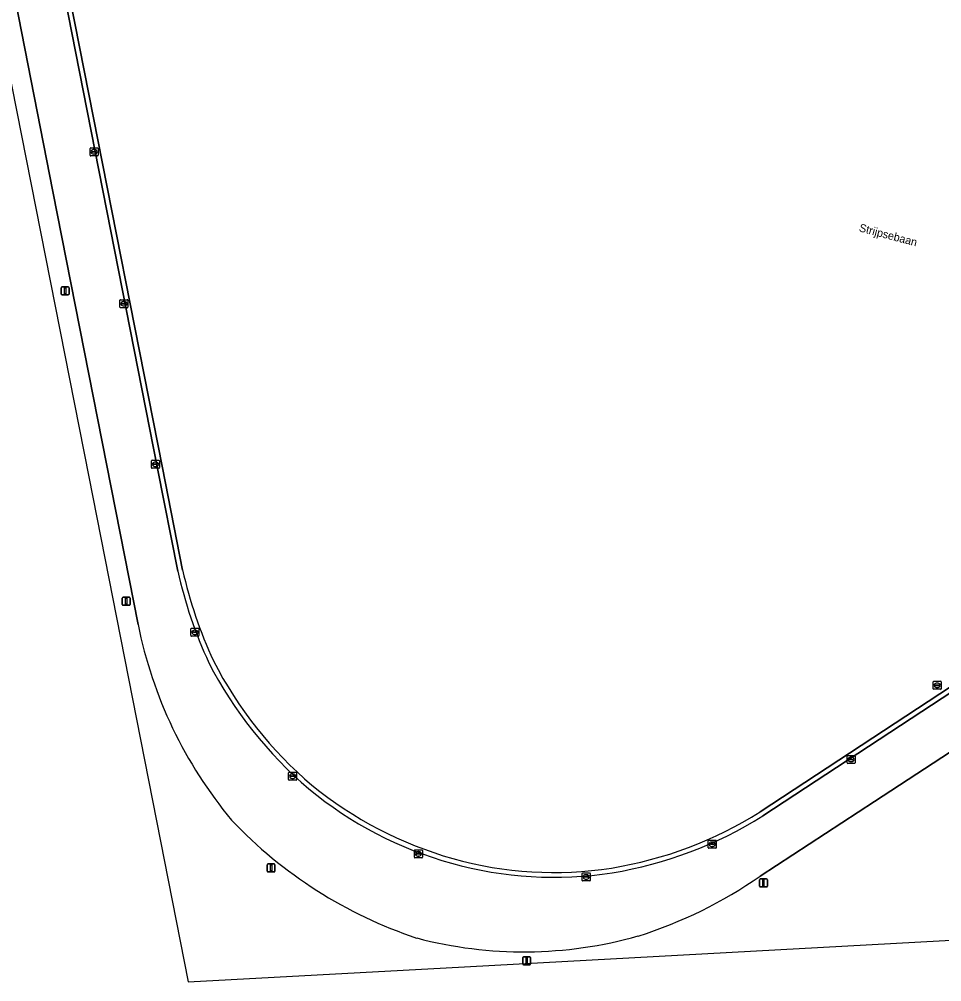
# Model space of a CAD drawing. Extents: x 154324 to 155744, y 382937 to 384188.
# Drawn here: x 154446.7 to 154562, y 382936.9 to 383057.2 of the extents above; entities that cross this region are included whole.
import ezdxf

# ---------------------------------------------------------------- set-up
doc = ezdxf.new("R2010")
doc.units = 0
for name, color, linetype in [('IMGEO_Bouwland', 7, 'Continuous'), ('IMGEO_Brandkraan', 7, 'Continuous'), ('IMGEO_Kolk', 7, 'Continuous'), ('IMGEO_Lichtmast', 7, 'Continuous'), ('IMGEO_Openbare_ruimte_label', 7, 'Continuous'), ('IMGEO_Rijbaan_lokaal_gesloten', 7, 'Continuous')]:
    doc.layers.add(name, color=color, linetype=linetype)

msp = doc.modelspace()

# ---------------------------------------------------------------- linework, layer by layer
at = {"layer": 'IMGEO_Bouwland'}
for points in [[(154461.51, 382981.55), (154450.87, 383035.65), (154439.15, 383095.25), (154422.31, 383181.22), (154406.72, 383260.28), (154396.48, 383312.17), (154394.42, 383322.32), (154392.95, 383329.96)], [(154562.03, 383175.54), (154561.39, 383175.43), (154560.93, 383178.26), (154468.8, 383162.6), (154469.46, 383158.8), (154442.14, 383154.08), (154422.8, 383252.54), (154415.36, 383251.02), (154421.39, 383220.37), (154444.99, 383100.45), (154464.56, 383001.13), (154467.07, 382988.35)], [(154438.84, 383056.38), (154444.54, 383054.87), (154455.34, 383000), (154467.76, 382936.91), (154500, 382938.67), (154564.68, 382942.19), (154564.68, 382942.19), (154613.01, 382968.97), (154623.86, 382975.26)], [(154539.26, 382958.13), (154607.95, 383003.23)], [(154607.05, 382994.38), (154553.54, 382959.42), (154539.25, 382950.1)]]:
    msp.add_lwpolyline(points, dxfattribs=at)
for centre, radius, start, end in [((154523.54, 383001.26), 57.93, 192.8711, 204.7457), ((154515.59, 382992.4), 55.16, 191.3377, 219.7864), ((154515.81, 382999.9), 50.38, 207.0226, 229.7267), ((154514.19, 382999.44), 48.99, 230.8269, 254.2103), ((154512.69, 383000.44), 49.96, 279.1993, 302.1275), ((154514.24, 382996.02), 56.56, 223.4828, 251.5325), ((154513.49, 382997.32), 46.76, 254.3311, 278.8421), ((154506.9, 382996.74), 56.76, 287.5622, 304.7459), ((154509.71, 382993.24), 52.59, 255.2615, 285.7936)]:
    msp.add_arc(centre, radius, start, end, dxfattribs=at)
at = {"layer": 'IMGEO_Brandkraan'}
for p, q in [((154560.89, 382973.52), (154560.89, 382974.37)), ((154560.96, 382974.45), (154561.81, 382974.45)), ((154561.89, 382974.37), (154561.89, 382973.52)), ((154561.81, 382973.45), (154560.96, 382973.45)), ((154561.14, 382973.94), (154561.14, 382973.95)), ((154561.58, 382973.9), (154561.18, 382973.9)), ((154561.19, 382973.99), (154561.59, 382973.99)), ((154561.37, 382974.23), (154561.4, 382974.23)), ((154561.4, 382973.67), (154561.37, 382973.67)), ((154561.63, 382973.95), (154561.63, 382973.94))]:
    msp.add_line(p, q, dxfattribs=at)
for points in [[(154560.89, 382973.52), (154560.89, 382974.37)], [(154560.96, 382974.45), (154561.81, 382974.45)], [(154561.89, 382974.37), (154561.89, 382973.52)], [(154561.81, 382973.45), (154560.96, 382973.45)]]:
    msp.add_lwpolyline(points, dxfattribs=at)
for centre, radius, start, end in [((154560.96, 382974.37), 0.0765, 91.552, 178.448), ((154560.96, 382974.37), 0.0765, 91.552, 178.448), ((154561.81, 382974.37), 0.0765, 1.552, 88.448), ((154561.81, 382974.37), 0.0765, 1.552, 88.448), ((154560.96, 382973.52), 0.0765, 181.552, 268.448), ((154560.96, 382973.52), 0.0765, 181.552, 268.448), ((154561.19, 382973.95), 0.0403, 85.8775, 175.7526), ((154561.18, 382973.94), 0.0366, 178.938, 274.7102), ((154561.59, 382973.95), 0.043, 264.8664, 352.4533), ((154561.59, 382973.95), 0.0386, 1.7309, 96.639), ((154561.81, 382973.52), 0.0765, 271.552, 358.448), ((154561.81, 382973.52), 0.0765, 271.552, 358.448)]:
    msp.add_arc(centre, radius, start, end, dxfattribs=at)
for centre, major_axis, ratio, start_param, end_param in [((154561.37, 382973.95), (-0.387, 0.002), 0.722429, 4.712389, 7.853982), ((154561.4, 382973.95), (-0.39, 0.002), 0.717154, 1.570796, 4.712389)]:
    msp.add_ellipse(centre, major_axis=major_axis, ratio=ratio, start_param=start_param, end_param=end_param, dxfattribs=at)
at = {"layer": 'IMGEO_Kolk'}
for p, q in [((154455.51, 383040.17), (154455.51, 383041.02)), ((154455.58, 383041.1), (154456.44, 383041.1)), ((154455.77, 383040.59), (154455.77, 383040.6)), ((154455.81, 383040.64), (154456.21, 383040.64)), ((154456.21, 383040.55), (154455.81, 383040.55)), ((154456, 383040.88), (154456.02, 383040.88)), ((154456.25, 383040.6), (154456.25, 383040.59)), ((154456.51, 383041.02), (154456.51, 383040.17)), ((154456.44, 383040.1), (154455.58, 383040.1)), ((154456.02, 383040.32), (154456, 383040.32)), ((154459.24, 383021.2), (154459.24, 383022.05)), ((154459.31, 383022.12), (154460.17, 383022.12)), ((154459.5, 383021.62), (154459.5, 383021.63)), ((154459.54, 383021.67), (154459.94, 383021.67)), ((154459.93, 383021.58), (154459.54, 383021.58)), ((154459.75, 383021.34), (154459.72, 383021.34)), ((154459.73, 383021.9), (154459.75, 383021.9)), ((154459.98, 383021.63), (154459.98, 383021.62)), ((154460.24, 383022.05), (154460.24, 383021.2)), ((154460.17, 383021.12), (154459.31, 383021.12)), ((154463.18, 383001.14), (154463.18, 383001.99)), ((154463.26, 383002.06), (154464.11, 383002.06)), ((154464.19, 383001.99), (154464.19, 383001.14)), ((154464.11, 383001.06), (154463.26, 383001.06)), ((154463.44, 383001.56), (154463.44, 383001.57)), ((154463.88, 383001.52), (154463.48, 383001.52)), ((154463.49, 383001.61), (154463.88, 383001.61)), ((154463.67, 383001.84), (154463.7, 383001.84)), ((154463.69, 383001.28), (154463.67, 383001.28)), ((154463.93, 383001.57), (154463.93, 383001.56)), ((154468.12, 382980.15), (154468.12, 382981)), ((154468.19, 382981.08), (154469.05, 382981.08)), ((154468.38, 382980.57), (154468.38, 382980.58)), ((154468.42, 382980.62), (154468.82, 382980.62)), ((154468.81, 382980.53), (154468.42, 382980.53)), ((154468.63, 382980.3), (154468.6, 382980.3)), ((154468.61, 382980.85), (154468.63, 382980.85)), ((154468.86, 382980.58), (154468.86, 382980.57)), ((154469.12, 382981), (154469.12, 382980.15)), ((154469.05, 382980.07), (154468.19, 382980.07)), ((154550.12, 382964.25), (154550.12, 382965.11)), ((154550.2, 382965.18), (154551.05, 382965.18)), ((154550.38, 382964.67), (154550.38, 382964.69)), ((154550.42, 382964.72), (154550.82, 382964.72)), ((154550.82, 382964.64), (154550.42, 382964.64)), ((154550.61, 382964.96), (154550.63, 382964.96)), ((154550.86, 382964.69), (154550.86, 382964.67)), ((154551.12, 382965.11), (154551.12, 382964.25)), ((154551.05, 382964.18), (154550.2, 382964.18)), ((154550.63, 382964.4), (154550.61, 382964.4)), ((154480.32, 382962.17), (154480.32, 382963.02)), ((154480.4, 382963.09), (154481.25, 382963.09)), ((154480.58, 382962.59), (154480.58, 382962.6)), ((154480.62, 382962.64), (154481.02, 382962.64)), ((154481.02, 382962.55), (154480.62, 382962.55)), ((154480.81, 382962.87), (154480.84, 382962.87)), ((154480.83, 382962.31), (154480.81, 382962.31)), ((154481.07, 382962.6), (154481.07, 382962.59)), ((154481.32, 382963.02), (154481.32, 382962.17)), ((154481.25, 382962.09), (154480.4, 382962.09)), ((154532.78, 382953.66), (154532.78, 382954.52)), ((154532.85, 382954.59), (154533.7, 382954.59)), ((154533.03, 382954.08), (154533.03, 382954.1)), ((154533.47, 382954.05), (154533.07, 382954.05)), ((154533.08, 382954.13), (154533.47, 382954.13)), ((154533.26, 382954.37), (154533.29, 382954.37)), ((154533.29, 382953.81), (154533.26, 382953.81)), ((154533.52, 382954.1), (154533.52, 382954.08)), ((154533.78, 382954.52), (154533.78, 382953.66)), ((154496.04, 382952.46), (154496.04, 382953.31)), ((154496.12, 382953.39), (154496.97, 382953.39)), ((154496.3, 382952.88), (154496.3, 382952.89)), ((154496.34, 382952.93), (154496.74, 382952.93)), ((154496.74, 382952.84), (154496.34, 382952.84)), ((154496.53, 382953.17), (154496.56, 382953.17)), ((154496.55, 382952.61), (154496.53, 382952.61)), ((154496.79, 382952.89), (154496.79, 382952.88)), ((154497.04, 382953.31), (154497.04, 382952.46)), ((154533.7, 382953.59), (154532.85, 382953.59)), ((154496.97, 382952.39), (154496.12, 382952.39)), ((154517.02, 382949.58), (154517.02, 382950.43)), ((154517.1, 382950.51), (154517.95, 382950.51)), ((154517.51, 382950.29), (154517.53, 382950.29)), ((154518.02, 382950.43), (154518.02, 382949.58)), ((154517.95, 382949.51), (154517.1, 382949.51)), ((154517.28, 382950), (154517.28, 382950.01)), ((154517.32, 382950.05), (154517.72, 382950.05)), ((154517.72, 382949.96), (154517.32, 382949.96)), ((154517.53, 382949.73), (154517.51, 382949.73)), ((154517.76, 382950.01), (154517.76, 382950))]:
    msp.add_line(p, q, dxfattribs=at)
for points in [[(154455.51, 383040.17), (154455.51, 383041.02)], [(154455.58, 383041.1), (154456.44, 383041.1)], [(154456.51, 383041.02), (154456.51, 383040.17)], [(154456.44, 383040.1), (154455.58, 383040.1)], [(154459.24, 383021.2), (154459.24, 383022.05)], [(154459.31, 383022.12), (154460.17, 383022.12)], [(154460.24, 383022.05), (154460.24, 383021.2)], [(154460.17, 383021.12), (154459.31, 383021.12)], [(154463.18, 383001.14), (154463.18, 383001.99)], [(154463.26, 383002.06), (154464.11, 383002.06)], [(154464.19, 383001.99), (154464.19, 383001.14)], [(154464.11, 383001.06), (154463.26, 383001.06)], [(154468.12, 382980.15), (154468.12, 382981)], [(154468.19, 382981.08), (154469.05, 382981.08)], [(154469.12, 382981), (154469.12, 382980.15)], [(154469.05, 382980.07), (154468.19, 382980.07)], [(154550.12, 382964.25), (154550.12, 382965.11)], [(154550.2, 382965.18), (154551.05, 382965.18)], [(154551.12, 382965.11), (154551.12, 382964.25)], [(154551.05, 382964.18), (154550.2, 382964.18)], [(154480.32, 382962.17), (154480.32, 382963.02)], [(154480.4, 382963.09), (154481.25, 382963.09)], [(154481.32, 382963.02), (154481.32, 382962.17)], [(154481.25, 382962.09), (154480.4, 382962.09)], [(154532.78, 382953.66), (154532.78, 382954.52)], [(154532.85, 382954.59), (154533.7, 382954.59)], [(154533.78, 382954.52), (154533.78, 382953.66)], [(154496.04, 382952.46), (154496.04, 382953.31)], [(154496.12, 382953.39), (154496.97, 382953.39)], [(154497.04, 382953.31), (154497.04, 382952.46)], [(154533.7, 382953.59), (154532.85, 382953.59)], [(154496.97, 382952.39), (154496.12, 382952.39)], [(154517.02, 382949.58), (154517.02, 382950.43)], [(154517.1, 382950.51), (154517.95, 382950.51)], [(154518.02, 382950.43), (154518.02, 382949.58)], [(154517.95, 382949.51), (154517.1, 382949.51)]]:
    msp.add_lwpolyline(points, dxfattribs=at)
for centre, radius, start, end in [((154455.59, 383041.02), 0.0765, 91.552, 178.448), ((154455.59, 383041.02), 0.0765, 91.552, 178.448), ((154455.81, 383040.6), 0.0403, 85.8775, 175.7526), ((154455.81, 383040.59), 0.0366, 178.938, 274.7102), ((154456.21, 383040.6), 0.0386, 1.7309, 96.639), ((154456.21, 383040.6), 0.043, 264.8664, 352.4533), ((154456.43, 383041.02), 0.0765, 1.552, 88.448), ((154456.43, 383041.02), 0.0765, 1.552, 88.448), ((154455.59, 383040.17), 0.0765, 181.552, 268.448), ((154455.59, 383040.17), 0.0765, 181.552, 268.448), ((154456.43, 383040.17), 0.0765, 271.552, 358.448), ((154456.43, 383040.17), 0.0765, 271.552, 358.448), ((154459.31, 383022.05), 0.0765, 91.552, 178.448), ((154459.31, 383022.05), 0.0765, 91.552, 178.448), ((154459.31, 383021.2), 0.0765, 181.552, 268.448), ((154459.31, 383021.2), 0.0765, 181.552, 268.448), ((154459.54, 383021.63), 0.0403, 85.8775, 175.7526), ((154459.53, 383021.62), 0.0366, 178.938, 274.7102), ((154459.94, 383021.62), 0.043, 264.8664, 352.4533), ((154459.94, 383021.63), 0.0386, 1.7309, 96.639), ((154460.16, 383022.05), 0.0765, 1.552, 88.448), ((154460.16, 383022.05), 0.0765, 1.552, 88.448), ((154460.16, 383021.2), 0.0765, 271.552, 358.448), ((154460.16, 383021.2), 0.0765, 271.552, 358.448), ((154463.26, 383001.99), 0.0765, 91.552, 178.448), ((154463.26, 383001.99), 0.0765, 91.552, 178.448), ((154464.11, 383001.99), 0.0765, 1.552, 88.448), ((154464.11, 383001.99), 0.0765, 1.552, 88.448), ((154463.26, 383001.14), 0.0765, 181.552, 268.448), ((154463.26, 383001.14), 0.0765, 181.552, 268.448), ((154463.48, 383001.57), 0.0403, 85.8775, 175.7526), ((154463.48, 383001.56), 0.0366, 178.938, 274.7102), ((154463.89, 383001.57), 0.0386, 1.7309, 96.639), ((154463.88, 383001.56), 0.043, 264.8664, 352.4533), ((154464.11, 383001.14), 0.0765, 271.552, 358.448), ((154464.11, 383001.14), 0.0765, 271.552, 358.448), ((154468.19, 382981), 0.0765, 91.552, 178.448), ((154468.19, 382981), 0.0765, 91.552, 178.448), ((154468.42, 382980.58), 0.0403, 85.8775, 175.7526), ((154468.41, 382980.57), 0.0366, 178.938, 274.7102), ((154468.82, 382980.57), 0.043, 264.8664, 352.4533), ((154468.82, 382980.58), 0.0386, 1.7309, 96.639), ((154469.04, 382981), 0.0765, 1.552, 88.448), ((154469.04, 382981), 0.0765, 1.552, 88.448), ((154468.19, 382980.15), 0.0765, 181.552, 268.448), ((154468.19, 382980.15), 0.0765, 181.552, 268.448), ((154469.04, 382980.15), 0.0765, 271.552, 358.448), ((154469.04, 382980.15), 0.0765, 271.552, 358.448), ((154550.2, 382965.1), 0.0765, 91.552, 178.448), ((154550.2, 382965.1), 0.0765, 91.552, 178.448), ((154550.42, 382964.68), 0.0403, 85.8775, 175.7526), ((154550.42, 382964.67), 0.0366, 178.938, 274.7102), ((154550.83, 382964.68), 0.0386, 1.7309, 96.639), ((154550.82, 382964.68), 0.043, 264.8664, 352.4533), ((154551.05, 382965.1), 0.0765, 1.552, 88.448), ((154551.05, 382965.1), 0.0765, 1.552, 88.448), ((154550.2, 382964.26), 0.0765, 181.552, 268.448), ((154550.2, 382964.26), 0.0765, 181.552, 268.448), ((154551.05, 382964.26), 0.0765, 271.552, 358.448), ((154551.05, 382964.26), 0.0765, 271.552, 358.448), ((154480.4, 382963.02), 0.0765, 91.552, 178.448), ((154480.4, 382963.02), 0.0765, 91.552, 178.448), ((154480.62, 382962.6), 0.0403, 85.8775, 175.7526), ((154480.62, 382962.59), 0.0366, 178.938, 274.7102), ((154481.03, 382962.6), 0.0386, 1.7309, 96.639), ((154481.02, 382962.59), 0.043, 264.8664, 352.4533), ((154481.25, 382963.02), 0.0765, 1.552, 88.448), ((154481.25, 382963.02), 0.0765, 1.552, 88.448), ((154480.4, 382962.17), 0.0765, 181.552, 268.448), ((154480.4, 382962.17), 0.0765, 181.552, 268.448), ((154481.25, 382962.17), 0.0765, 271.552, 358.448), ((154481.25, 382962.17), 0.0765, 271.552, 358.448), ((154532.85, 382954.52), 0.0765, 91.552, 178.448), ((154532.85, 382954.52), 0.0765, 91.552, 178.448), ((154533.07, 382954.09), 0.0403, 85.8775, 175.7526), ((154533.07, 382954.08), 0.0366, 178.938, 274.7102), ((154533.48, 382954.1), 0.0386, 1.7309, 96.639), ((154533.48, 382954.09), 0.043, 264.8664, 352.4533), ((154533.7, 382954.52), 0.0765, 1.552, 88.448), ((154533.7, 382954.52), 0.0765, 1.552, 88.448), ((154496.12, 382953.31), 0.0765, 91.552, 178.448), ((154496.12, 382953.31), 0.0765, 91.552, 178.448), ((154496.34, 382952.89), 0.0403, 85.8775, 175.7526), ((154496.34, 382952.88), 0.0366, 178.938, 274.7102), ((154496.75, 382952.89), 0.0386, 1.7309, 96.639), ((154496.74, 382952.89), 0.043, 264.8664, 352.4533), ((154496.97, 382953.31), 0.0765, 1.552, 88.448), ((154496.97, 382953.31), 0.0765, 1.552, 88.448), ((154532.85, 382953.67), 0.0765, 181.552, 268.448), ((154532.85, 382953.67), 0.0765, 181.552, 268.448), ((154533.7, 382953.67), 0.0765, 271.552, 358.448), ((154533.7, 382953.67), 0.0765, 271.552, 358.448), ((154496.12, 382952.46), 0.0765, 181.552, 268.448), ((154496.12, 382952.46), 0.0765, 181.552, 268.448), ((154496.97, 382952.46), 0.0765, 271.552, 358.448), ((154496.97, 382952.46), 0.0765, 271.552, 358.448), ((154517.1, 382950.43), 0.0765, 91.552, 178.448), ((154517.1, 382950.43), 0.0765, 91.552, 178.448), ((154517.95, 382950.43), 0.0765, 1.552, 88.448), ((154517.95, 382950.43), 0.0765, 1.552, 88.448), ((154517.1, 382949.58), 0.0765, 181.552, 268.448), ((154517.1, 382949.58), 0.0765, 181.552, 268.448), ((154517.32, 382950.01), 0.0403, 85.8775, 175.7526), ((154517.32, 382950), 0.0366, 178.938, 274.7102), ((154517.73, 382950.01), 0.0386, 1.7309, 96.639), ((154517.72, 382950.01), 0.043, 264.8664, 352.4533), ((154517.95, 382949.58), 0.0765, 271.552, 358.448), ((154517.95, 382949.58), 0.0765, 271.552, 358.448)]:
    msp.add_arc(centre, radius, start, end, dxfattribs=at)
for centre, major_axis, ratio, start_param, end_param in [((154456, 383040.6), (-0.387, 0.002), 0.722429, 4.712389, 7.853982), ((154456.02, 383040.6), (-0.39, 0.002), 0.717154, 1.570796, 4.712389), ((154459.73, 383021.62), (-0.387, 0.002), 0.722429, 4.712389, 7.853982), ((154459.75, 383021.62), (-0.39, 0.002), 0.717154, 1.570796, 4.712389), ((154463.67, 383001.56), (-0.387, 0.002), 0.722429, 4.712389, 7.853982), ((154463.7, 383001.56), (-0.39, 0.002), 0.717154, 1.570796, 4.712389), ((154468.61, 382980.57), (-0.387, 0.002), 0.722429, 4.712389, 7.853982), ((154468.63, 382980.57), (-0.39, 0.002), 0.717154, 1.570796, 4.712389), ((154550.61, 382964.68), (-0.387, 0.002), 0.722429, 4.712389, 7.853982), ((154550.63, 382964.68), (-0.39, 0.002), 0.717154, 1.570796, 4.712389), ((154480.81, 382962.59), (-0.387, 0.002), 0.722429, 4.712389, 7.853982), ((154480.83, 382962.59), (-0.39, 0.002), 0.717154, 1.570796, 4.712389), ((154533.26, 382954.09), (-0.387, 0.002), 0.722429, 4.712389, 7.853982), ((154533.29, 382954.09), (-0.39, 0.002), 0.717154, 1.570796, 4.712389), ((154496.53, 382952.89), (-0.387, 0.002), 0.722429, 4.712389, 7.853982), ((154496.55, 382952.89), (-0.39, 0.002), 0.717154, 1.570796, 4.712389), ((154517.51, 382950.01), (-0.387, 0.002), 0.722429, 4.712389, 7.853982), ((154517.53, 382950.01), (-0.39, 0.002), 0.717154, 1.570796, 4.712389)]:
    msp.add_ellipse(centre, major_axis=major_axis, ratio=ratio, start_param=start_param, end_param=end_param, dxfattribs=at)
at = {"layer": 'IMGEO_Lichtmast'}
for p, q in [((154451.89, 383022.83), (154451.89, 383023.62)), ((154451.89, 383023.62), (154451.89, 383022.83)), ((154451.99, 383023.72), (154452.78, 383023.72)), ((154452.78, 383023.72), (154451.99, 383023.72)), ((154452.88, 383023.62), (154452.88, 383022.83)), ((154452.88, 383022.83), (154452.88, 383023.62)), ((154452.78, 383022.73), (154451.99, 383022.73)), ((154451.99, 383022.73), (154452.78, 383022.73)), ((154459.53, 382984.05), (154459.53, 382984.85)), ((154459.53, 382984.85), (154459.53, 382984.05)), ((154459.63, 382984.95), (154460.42, 382984.95)), ((154460.42, 382984.95), (154459.63, 382984.95)), ((154460.42, 382983.95), (154459.63, 382983.95)), ((154459.63, 382983.95), (154460.42, 382983.95)), ((154460.52, 382984.85), (154460.52, 382984.05)), ((154460.52, 382984.05), (154460.52, 382984.85)), ((154477.64, 382950.73), (154477.64, 382951.53)), ((154477.64, 382951.53), (154477.64, 382950.73)), ((154477.74, 382951.63), (154478.52, 382951.63)), ((154478.52, 382951.63), (154477.74, 382951.63)), ((154478.62, 382951.53), (154478.62, 382950.73)), ((154478.62, 382950.73), (154478.62, 382951.53)), ((154478.52, 382950.63), (154477.74, 382950.63)), ((154477.74, 382950.63), (154478.52, 382950.63)), ((154539.17, 382948.86), (154539.17, 382949.66)), ((154539.17, 382949.66), (154539.17, 382948.86)), ((154539.27, 382949.76), (154540.06, 382949.76)), ((154540.06, 382949.76), (154539.27, 382949.76)), ((154540.16, 382949.66), (154540.16, 382948.86)), ((154540.16, 382948.86), (154540.16, 382949.66)), ((154540.06, 382948.76), (154539.27, 382948.76)), ((154539.27, 382948.76), (154540.06, 382948.76)), ((154509.58, 382939.13), (154509.58, 382939.93)), ((154509.58, 382939.93), (154509.58, 382939.13)), ((154509.68, 382940.03), (154510.47, 382940.03)), ((154510.47, 382940.03), (154509.68, 382940.03)), ((154510.57, 382939.93), (154510.57, 382939.13)), ((154510.57, 382939.13), (154510.57, 382939.93)), ((154510.47, 382939.03), (154509.68, 382939.03)), ((154509.68, 382939.03), (154510.47, 382939.03))]:
    msp.add_line(p, q, dxfattribs=at)
for points in [[(154452.31, 383023.6), (154452.46, 383023.6), (154452.46, 383022.85), (154452.31, 383022.85), (154452.31, 383023.6)], [(154459.95, 382984.83), (154460.1, 382984.83), (154460.1, 382984.08), (154459.95, 382984.08), (154459.95, 382984.83)], [(154478.05, 382951.51), (154478.21, 382951.51), (154478.21, 382950.76), (154478.05, 382950.76), (154478.05, 382951.51)], [(154539.59, 382949.63), (154539.74, 382949.63), (154539.74, 382948.88), (154539.59, 382948.88), (154539.59, 382949.63)], [(154510, 382939.9), (154510.15, 382939.9), (154510.15, 382939.15), (154510, 382939.15), (154510, 382939.9)]]:
    msp.add_lwpolyline(points, dxfattribs=at)
for centre, start, end in [((154451.99, 383023.62), 90, 180), ((154451.99, 383023.62), 90, 180), ((154452.78, 383023.62), 0, 90), ((154452.78, 383023.62), 360, 90), ((154451.99, 383022.83), 180, 270), ((154451.99, 383022.83), 180, 270), ((154452.78, 383022.83), 270, 0), ((154452.78, 383022.83), 270, 0), ((154459.63, 382984.85), 90, 180), ((154459.63, 382984.85), 90, 180), ((154459.63, 382984.05), 180, 270), ((154459.63, 382984.05), 180, 270), ((154460.42, 382984.85), 0, 90), ((154460.42, 382984.85), 360, 90), ((154460.42, 382984.05), 270, 0), ((154460.42, 382984.05), 270, 0), ((154477.74, 382951.53), 90, 180), ((154477.74, 382951.53), 90, 180), ((154478.52, 382951.53), 0, 90), ((154478.52, 382951.53), 360, 90), ((154477.74, 382950.73), 180, 270), ((154477.74, 382950.73), 180, 270), ((154478.52, 382950.73), 270, 0), ((154478.52, 382950.73), 270, 0), ((154539.27, 382949.66), 90, 180), ((154539.27, 382949.66), 90, 180), ((154540.06, 382949.66), 0, 90), ((154540.06, 382949.66), 360, 90), ((154539.27, 382948.86), 180, 270), ((154539.27, 382948.86), 180, 270), ((154540.06, 382948.86), 270, 0), ((154540.06, 382948.86), 270, 0), ((154509.68, 382939.93), 90, 180), ((154509.68, 382939.93), 90, 180), ((154510.47, 382939.93), 0, 90), ((154510.47, 382939.93), 360, 90), ((154509.68, 382939.13), 180, 270), ((154509.68, 382939.13), 180, 270), ((154510.47, 382939.13), 270, 0), ((154510.47, 382939.13), 270, 0)]:
    msp.add_arc(centre, 0.1, start, end, dxfattribs=at)
at = {"layer": 'IMGEO_Rijbaan_lokaal_gesloten'}
for points in [[(154392.95, 383329.96), (154394.42, 383322.32), (154396.48, 383312.17), (154406.72, 383260.28), (154422.31, 383181.22), (154439.15, 383095.25), (154450.87, 383035.65), (154461.51, 382981.55)], [(154400.66, 383322.48), (154411.51, 383267.43), (154432.24, 383162.26), (154453.69, 383053.15), (154463.94, 383001.02), (154466.46, 382988.22)], [(154466.46, 382988.22), (154463.94, 383001.02), (154453.69, 383053.15), (154432.24, 383162.26), (154411.51, 383267.43), (154400.66, 383322.48)], [(154467.07, 382988.35), (154464.56, 383001.13), (154444.99, 383100.45), (154421.39, 383220.37), (154415.36, 383251.02), (154401.25, 383322.6)], [(154607.95, 383003.23), (154539.26, 382958.13)], [(154539.6, 382957.62), (154608.29, 383002.71)], [(154608.29, 383002.71), (154539.6, 382957.62)], [(154539.25, 382950.1), (154553.54, 382959.42), (154607.05, 382994.38)]]:
    msp.add_lwpolyline(points, dxfattribs=at)
for centre, radius, start, end in [((154522.78, 383000.96), 57.74, 192.7495, 204.7878), ((154522.78, 383000.96), 57.74, 192.7495, 204.7878), ((154523.54, 383001.26), 57.93, 192.8711, 204.7457), ((154515.59, 382992.4), 55.16, 191.3377, 219.7864), ((154516.28, 383000.38), 51.64, 207.2284, 229.6764), ((154516.28, 383000.38), 51.64, 207.2284, 229.6764), ((154515.81, 382999.9), 50.38, 207.0226, 229.7267), ((154514.19, 382999.44), 48.99, 230.8269, 254.2103), ((154513.68, 382998.4), 48.46, 230.5036, 254.4383), ((154513.68, 382998.4), 48.46, 230.5036, 254.4383), ((154512.69, 383000.44), 49.96, 279.1993, 302.1275), ((154512.32, 383001.51), 51.68, 279.3989, 301.8697), ((154512.32, 383001.51), 51.68, 279.3989, 301.8697), ((154514.24, 382996.02), 56.56, 223.4828, 251.5325), ((154513.49, 382997.42), 47.46, 254.3399, 278.801), ((154513.49, 382997.42), 47.46, 254.3399, 278.801), ((154513.49, 382997.32), 46.76, 254.3311, 278.8421), ((154506.9, 382996.74), 56.76, 287.5622, 304.7459), ((154509.71, 382993.24), 52.59, 255.2615, 285.7936)]:
    msp.add_arc(centre, radius, start, end, dxfattribs=at)

# ---------------------------------------------------------------- texts
at = {"layer": 'IMGEO_Openbare_ruimte_label'}
msp.add_text('Strijpsebaan', height=1, rotation=345.1719, dxfattribs=at).set_placement((154551.55, 383030.68))

doc.saveas('drawing.dxf')
